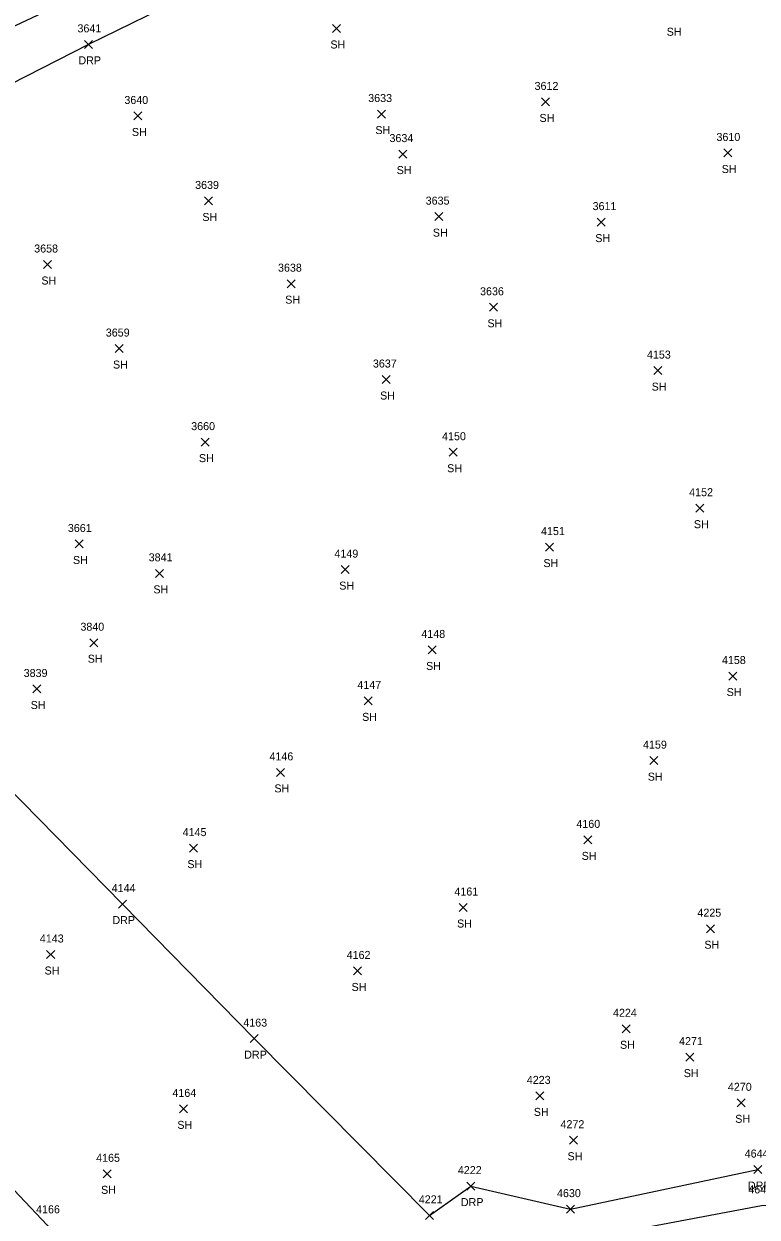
# Model space of a CAD drawing. Extents: x 1472233 to 1475777, y 540726 to 543442.
# Drawn here: x 1474636.5 to 1474819.6, y 541774.4 to 542072.6 of the extents above; entities that cross this region are included whole.
import ezdxf

# ---------------------------------------------------------------- set-up
doc = ezdxf.new("R2010")
doc.units = 0
for name, color, linetype in [('L_A', 7, 'Continuous'), ('L_I', 7, 'Continuous'), ('L_TIC', 7, 'Continuous'), ('LELB', 7, 'Continuous'), ('R_A', 7, 'Continuous'), ('R_I', 7, 'Continuous'), ('R_TIC', 7, 'Continuous'), ('RDP', 7, 'Continuous')]:
    doc.layers.add(name, color=color, linetype=linetype)

msp = doc.modelspace()

# ---------------------------------------------------------------- linework, layer by layer
at = {"layer": 'L_TIC'}
for points in [[(1474713.58, 542070.48), (1474715.58, 542072.48)], [(1474715.58, 542070.48), (1474713.58, 542072.48)], [(1474765.8, 542052.12), (1474767.8, 542054.12)], [(1474767.8, 542052.12), (1474765.8, 542054.12)], [(1474664, 542048.61), (1474666, 542050.61)], [(1474666, 542048.61), (1474664, 542050.61)], [(1474724.81, 542049.09), (1474726.81, 542051.09)], [(1474726.81, 542049.09), (1474724.81, 542051.09)], [(1474730.12, 542039.08), (1474732.12, 542041.08)], [(1474732.12, 542039.08), (1474730.12, 542041.08)], [(1474811.31, 542039.36), (1474813.31, 542041.36)], [(1474813.31, 542039.36), (1474811.31, 542041.36)], [(1474681.6, 542027.37), (1474683.6, 542029.37)], [(1474683.6, 542027.37), (1474681.6, 542029.37)], [(1474739.16, 542023.45), (1474741.16, 542025.45)], [(1474741.16, 542023.45), (1474739.16, 542025.45)], [(1474779.72, 542022.08), (1474781.72, 542024.08)], [(1474781.72, 542022.08), (1474779.72, 542024.08)], [(1474641.4, 542011.48), (1474643.4, 542013.48)], [(1474643.4, 542011.48), (1474641.4, 542013.48)], [(1474702.29, 542006.69), (1474704.29, 542008.69)], [(1474704.29, 542006.69), (1474702.29, 542008.69)], [(1474752.8, 542000.79), (1474754.8, 542002.79)], [(1474754.8, 542000.79), (1474752.8, 542002.79)], [(1474659.28, 541990.47), (1474661.28, 541992.47)], [(1474661.28, 541990.47), (1474659.28, 541992.47)], [(1474725.99, 541982.73), (1474727.99, 541984.73)], [(1474727.99, 541982.73), (1474725.99, 541984.73)], [(1474793.81, 541984.96), (1474795.81, 541986.96)], [(1474795.81, 541984.96), (1474793.81, 541986.96)], [(1474680.75, 541967.08), (1474682.75, 541969.08)], [(1474682.75, 541967.08), (1474680.75, 541969.08)], [(1474742.74, 541964.56), (1474744.74, 541966.56)], [(1474744.74, 541964.56), (1474742.74, 541966.56)], [(1474804.37, 541950.57), (1474806.37, 541952.57)], [(1474806.37, 541950.57), (1474804.37, 541952.57)], [(1474649.28, 541941.62), (1474651.28, 541943.62)], [(1474651.28, 541941.62), (1474649.28, 541943.62)], [(1474766.79, 541940.85), (1474768.79, 541942.85)], [(1474768.79, 541940.85), (1474766.79, 541942.85)], [(1474715.78, 541935.22), (1474717.78, 541937.22)], [(1474717.78, 541935.22), (1474715.78, 541937.22)], [(1474669.38, 541934.28), (1474671.38, 541936.28)], [(1474671.38, 541934.28), (1474669.38, 541936.28)], [(1474652.97, 541916.94), (1474654.97, 541918.94)], [(1474654.97, 541916.94), (1474652.97, 541918.94)], [(1474737.48, 541915.14), (1474739.48, 541917.14)], [(1474739.48, 541915.14), (1474737.48, 541917.14)], [(1474812.54, 541908.61), (1474814.54, 541910.61)], [(1474814.54, 541908.61), (1474812.54, 541910.61)], [(1474638.72, 541905.38), (1474640.72, 541907.38)], [(1474640.72, 541905.38), (1474638.72, 541907.38)], [(1474721.5, 541902.41), (1474723.5, 541904.41)], [(1474723.5, 541902.41), (1474721.5, 541904.41)], [(1474792.85, 541887.47), (1474794.85, 541889.47)], [(1474794.85, 541887.47), (1474792.85, 541889.47)], [(1474699.59, 541884.53), (1474701.59, 541886.53)], [(1474701.59, 541884.53), (1474699.59, 541886.53)], [(1474776.33, 541867.66), (1474778.33, 541869.66)], [(1474778.33, 541867.66), (1474776.33, 541869.66)], [(1474677.85, 541865.6), (1474679.85, 541867.6)], [(1474679.85, 541865.6), (1474677.85, 541867.6)], [(1474745.21, 541850.75), (1474747.21, 541852.75)], [(1474747.21, 541850.75), (1474745.21, 541852.75)], [(1474806.99, 541845.46), (1474808.99, 541847.46)], [(1474808.99, 541845.46), (1474806.99, 541847.46)], [(1474642.2, 541839.01), (1474644.2, 541841.01)], [(1474644.2, 541839.01), (1474642.2, 541841.01)], [(1474718.87, 541834.9), (1474720.87, 541836.9)], [(1474720.87, 541834.9), (1474718.87, 541836.9)], [(1474785.91, 541820.44), (1474787.91, 541822.44)], [(1474787.91, 541820.44), (1474785.91, 541822.44)], [(1474801.85, 541813.36), (1474803.85, 541815.36)], [(1474803.85, 541813.36), (1474801.85, 541815.36)], [(1474764.38, 541803.67), (1474766.38, 541805.67)], [(1474766.38, 541803.67), (1474764.38, 541805.67)], [(1474675.35, 541800.42), (1474677.35, 541802.42)], [(1474677.35, 541800.42), (1474675.35, 541802.42)], [(1474814.68, 541801.94), (1474816.68, 541803.94)], [(1474816.68, 541801.94), (1474814.68, 541803.94)], [(1474772.8, 541792.59), (1474774.8, 541794.59)], [(1474774.8, 541792.59), (1474772.8, 541794.59)], [(1474656.3, 541784.19), (1474658.3, 541786.19)], [(1474658.3, 541784.19), (1474656.3, 541786.19)]]:
    msp.add_lwpolyline(points, dxfattribs=at)
at = {"layer": 'LELB'}
for points in [[(1474646.7, 542077.97), (1474605.73, 542058.69), (1474564.37, 542030.09), (1474534.06, 542007.71), (1474534.27, 542002.7), (1474537.92, 541986.42), (1474527.62, 541968.83), (1474514.64, 541938.04), (1474505.9, 541935.02), (1474501.26, 541912.42), (1474545, 541874.82), (1474574.44, 541841.14), (1474607.71, 541809.02), (1474642.36, 541772.32), (1474675.9, 541726.31), (1474702.74, 541707.64), (1474726.2, 541708.9)], [(1474748.43, 541762), (1474774.4, 541768.54), (1474820.73, 541777.29), (1474855.67, 541778.07), (1474873.51, 541779.06), (1474873.8, 541760.35), (1474868.37, 541746.85), (1474863.74, 541730.16)]]:
    msp.add_lwpolyline(points, dxfattribs=at)
at = {"layer": 'R_TIC'}
for points in [[(1474651.64, 542066.51), (1474653.64, 542068.51)], [(1474653.64, 542066.51), (1474651.64, 542068.51)], [(1474660.13, 541851.61), (1474662.13, 541853.61)], [(1474662.13, 541851.61), (1474660.13, 541853.61)], [(1474693.05, 541817.98), (1474695.05, 541819.98)], [(1474695.05, 541817.98), (1474693.05, 541819.98)], [(1474818.85, 541785.26), (1474820.85, 541787.26)], [(1474820.85, 541785.26), (1474818.85, 541787.26)], [(1474747.16, 541781.12), (1474749.16, 541783.12)], [(1474749.16, 541781.12), (1474747.16, 541783.12)], [(1474736.83, 541773.81), (1474738.83, 541775.81)], [(1474738.83, 541773.81), (1474736.83, 541775.81)], [(1474772.05, 541775.36), (1474774.05, 541777.36)], [(1474774.05, 541775.36), (1474772.05, 541777.36)]]:
    msp.add_lwpolyline(points, dxfattribs=at)
at = {"layer": 'RDP'}
msp.add_lwpolyline([(1474703.06, 542092.25), (1474652.64, 542067.51), (1474613.6, 542047.52), (1474568.89, 542023.05), (1474536.75, 542005.37), (1474553.11, 541988.56), (1474586.1, 541954.87), (1474574.62, 541942.46), (1474593.14, 541922.25), (1474623.44, 541891.04), (1474661.13, 541852.61), (1474694.05, 541818.98), (1474737.83, 541774.81), (1474748.16, 541782.12), (1474773.05, 541776.36), (1474819.85, 541786.26)], dxfattribs=at)

# ---------------------------------------------------------------- texts
at = {"layer": 'L_A'}
for p in [(1474797.05, 542069.66), (1474713.07, 542066.48), (1474765.29, 542048.12), (1474724.3, 542045.09), (1474663.49, 542044.61), (1474729.61, 542035.08), (1474810.8, 542035.36), (1474681.09, 542023.37), (1474738.65, 542019.45), (1474779.21, 542018.08), (1474640.89, 542007.48), (1474701.78, 542002.69), (1474752.29, 541996.79), (1474658.77, 541986.47), (1474793.3, 541980.96), (1474725.48, 541978.73), (1474680.23, 541963.08), (1474742.23, 541960.56), (1474803.85, 541946.57), (1474648.77, 541937.62), (1474766.28, 541936.85), (1474668.86, 541930.28), (1474715.27, 541931.22), (1474652.46, 541912.94), (1474736.96, 541911.14), (1474812.03, 541904.61), (1474638.21, 541901.38), (1474720.99, 541898.41), (1474792.34, 541883.47), (1474699.08, 541880.53), (1474775.82, 541863.66), (1474677.34, 541861.6), (1474744.7, 541846.75), (1474806.47, 541841.46), (1474641.68, 541835.01), (1474718.36, 541830.9), (1474785.4, 541816.44), (1474801.33, 541809.36), (1474763.87, 541799.67), (1474814.17, 541797.94), (1474674.84, 541796.42), (1474772.29, 541788.59), (1474655.79, 541780.19)]:
    msp.add_text('SH', height=2, dxfattribs=at).set_placement(p)
at = {"layer": 'L_I'}
for s, p in [('3612', (1474764.06, 542056.12)), ('3640', (1474661.61, 542052.61)), ('3633', (1474722.51, 542053.09)), ('3634', (1474727.82, 542043.08)), ('3610', (1474809.49, 542043.36)), ('3639', (1474679.28, 542031.37)), ('3635', (1474736.86, 542027.45)), ('3611', (1474778.55, 542026.08)), ('3658', (1474639.09, 542015.48)), ('3638', (1474699.98, 542010.69)), ('3636', (1474750.44, 542004.79)), ('3659', (1474656.97, 541994.47)), ('4153', (1474792.12, 541988.96)), ('3637', (1474723.68, 541986.73)), ('3660', (1474678.3, 541971.08)), ('4150', (1474740.96, 541968.56)), ('4152', (1474802.67, 541954.57)), ('3661', (1474647.5, 541945.62)), ('4151', (1474765.67, 541944.85)), ('3841', (1474667.68, 541938.28)), ('4149', (1474714.08, 541939.22)), ('3840', (1474650.63, 541920.94)), ('4148', (1474735.78, 541919.14)), ('4158', (1474810.85, 541912.61)), ('3839', (1474636.46, 541909.38)), ('4147', (1474719.81, 541906.41)), ('4159', (1474791.15, 541891.47)), ('4146', (1474697.85, 541888.53)), ('4145', (1474676.16, 541869.6)), ('4160', (1474774.5, 541871.66)), ('4161', (1474744.04, 541854.75)), ('4225', (1474804.73, 541849.46)), ('4143', (1474640.5, 541843.01)), ('4162', (1474717.13, 541838.9)), ('4224', (1474783.65, 541824.44)), ('4271', (1474800.15, 541817.36)), ('4223', (1474762.12, 541807.67)), ('4164', (1474673.61, 541804.42)), ('4270', (1474812.34, 541805.94)), ('4272', (1474770.54, 541796.59)), ('4165', (1474654.56, 541788.19)), ('4643', (1474817.43, 541780.29)), ('4166', (1474639.56, 541775.32))]:
    msp.add_text(s, height=2, dxfattribs=at).set_placement(p)
at = {"layer": 'R_A'}
for p in [(1474650.13, 542062.51), (1474658.62, 541847.61), (1474691.54, 541813.98), (1474817.34, 541781.26), (1474745.65, 541777.12)]:
    msp.add_text('DRP', height=2, dxfattribs=at).set_placement(p)
at = {"layer": 'R_I'}
for s, p in [('3641', (1474649.9, 542070.51)), ('4144', (1474658.44, 541855.61)), ('4163', (1474691.31, 541821.98)), ('4644', (1474816.54, 541789.26)), ('4222', (1474744.9, 541785.12)), ('4630', (1474769.66, 541779.36)), ('4221', (1474735.14, 541777.81))]:
    msp.add_text(s, height=2, dxfattribs=at).set_placement(p)

doc.saveas('drawing.dxf')
